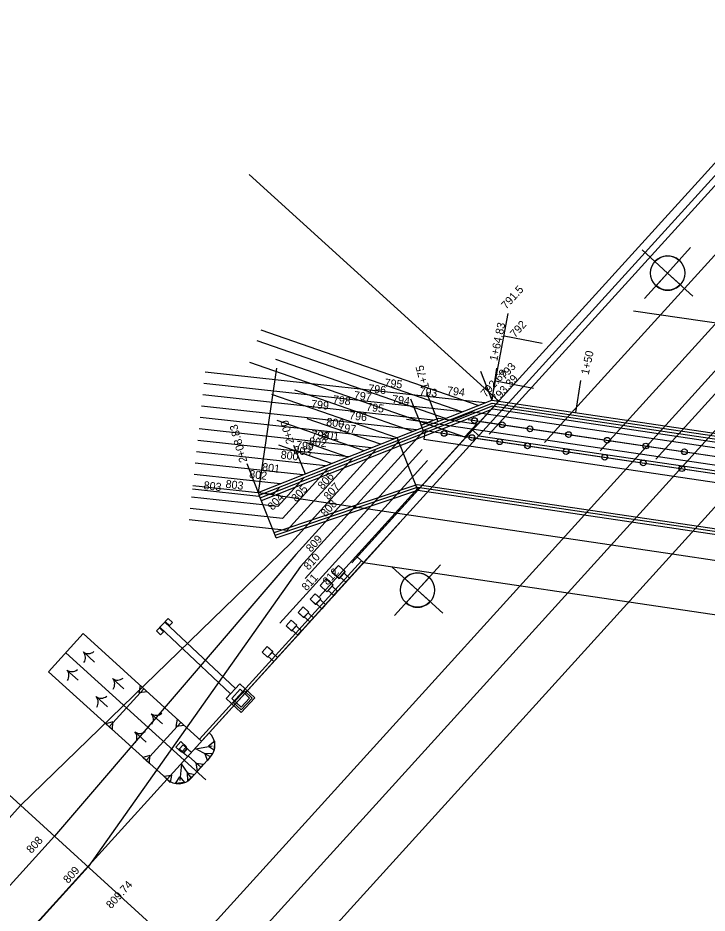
# Model space of a CAD drawing. Extents: x 1465887 to 1476191, y 569684 to 581027.
# Drawn here: x 1469715.4 to 1469836.1, y 573949.1 to 574105.8 of the extents above; entities that cross this region are included whole.
import ezdxf

# ---------------------------------------------------------------- set-up
doc = ezdxf.new("R2010")
doc.units = 0
for name, color, linetype in [('BR_P_Beam_Centerline', 7, 'Continuous'), ('BR_P_Brg_Centerline', 7, 'Continuous'), ('BR_P_Gen_Approach_Slab', 7, 'Continuous'), ('BR_P_Gen_Ground_Slope', 7, 'Continuous'), ('BR_P_Gen_Perforated_Pipe', 7, 'Continuous'), ('BR_P_Gen_Porous_Backfill', 7, 'Continuous'), ('BR_P_Gen_Profile_Grade', 7, 'Continuous'), ('BR_P_Gen_Slope_Protection', 7, 'Continuous'), ('BR_P_Rail_Object', 7, 'Continuous'), ('BR_P_Sub_Deep_Centerline', 7, 'Continuous'), ('BR_P_Sub_Deep_Hidden', 7, 'Continuous'), ('BR_P_Sub_Foot_Hidden', 7, 'Continuous'), ('BR_P_Sub_Hidden', 7, 'Continuous'), ('BR_P_Sub_Object', 7, 'Continuous'), ('BR_X_Sub_Hidden', 7, 'Continuous'), ('Default', 7, 'Continuous'), ('DR_P_Cells', 7, 'Continuous'), ('DR_P_Ditch', 7, 'Continuous'), ('DR_P_Erosion_Control', 7, 'Continuous'), ('DR_P_Headwall', 7, 'Continuous'), ('DR_P_Paved_Gutter', 7, 'Continuous'), ('DR_P_Storm_Sewer', 7, 'Continuous'), ('GK_Drainage_Nodes', 7, 'Continuous'), ('GT_Project_Soil_Boring', 7, 'Continuous'), ('RD_P_Anchor_Assembly', 7, 'Continuous'), ('SC_Scratch1', 7, 'Continuous'), ('SC_Scratch2', 7, 'Continuous')]:
    doc.layers.add(name, color=color, linetype=linetype)

msp = doc.modelspace()

# ---------------------------------------------------------------- linework, layer by layer
at = {"layer": 'BR_P_Beam_Centerline'}
for p, q in [((1469797.88, 574032.91), (1469908.95, 574155.21)), ((1469807.6, 574031.47), (1469918.67, 574153.77)), ((1469817.33, 574030.03), (1469928.4, 574152.33)), ((1469827.05, 574028.59), (1469938.12, 574150.89))]:
    msp.add_line(p, q, dxfattribs=at)
at = {"layer": 'BR_P_Brg_Centerline'}
msp.add_line((1469783.43, 574035.55), (1469948.19, 574011.16), dxfattribs=at)
at = {"layer": 'BR_P_Gen_Approach_Slab'}
for p, q in [((1469796.09, 574032.67), (1469935.4, 574012.04)), ((1469775.92, 574010.46), (1469915.23, 573989.83))]:
    msp.add_line(p, q, dxfattribs=at)
at = {"layer": 'BR_P_Gen_Ground_Slope'}
for p, q in [((1469798.37, 574038.9), (1469801.25, 574054.05)), ((1469795.95, 574037.94), (1469757.95, 574051.14)), ((1469800.5, 574050.12), (1469807.16, 574048.86)), ((1469793.1, 574036.82), (1469757.29, 574049.25)), ((1469793.98, 574032.28), (1469755.98, 574045.47)), ((1469790.25, 574035.69), (1469760.55, 574046)), ((1469797.14, 574038.41), (1469748.18, 574043.79)), ((1469793.15, 574036.84), (1469747.96, 574041.8)), ((1469799.01, 574042.26), (1469805.67, 574041)), ((1469784.55, 574033.43), (1469763.85, 574040.62)), ((1469788.11, 574035.38), (1469747.75, 574039.81)), ((1469781.7, 574032.31), (1469759.84, 574039.9)), ((1469785.19, 574033.69), (1469747.53, 574037.82)), ((1469781.21, 574032.11), (1469747.31, 574035.84)), ((1469778.85, 574031.18), (1469766, 574035.64)), ((1469776, 574030.05), (1469760.78, 574035.34)), ((1469777.23, 574030.54), (1469747.09, 574033.85)), ((1469786.61, 574033.71), (1469764.86, 574009.76)), ((1469773.25, 574028.96), (1469746.87, 574031.86)), ((1469770.3, 574027.8), (1469761.04, 574031.01)), ((1469782.39, 574032.04), (1469764.06, 574011.86)), ((1469773.15, 574028.93), (1469765.78, 574031.49)), ((1469769.26, 574027.39), (1469746.65, 574029.87)), ((1469778.17, 574030.38), (1469763.27, 574013.96)), ((1469786.16, 574030.24), (1469765.66, 574007.67)), ((1469765.28, 574025.81), (1469746.44, 574027.88)), ((1469787.11, 574028.32), (1469761.25, 573999.84)), ((1469773.96, 574028.71), (1469762.47, 574016.06)), ((1469769.74, 574027.04), (1469761.68, 574018.16)), ((1469761.3, 574024.24), (1469746.22, 574025.9)), ((1469765.53, 574025.37), (1469760.88, 574020.26)), ((1469757.58, 574022.04), (1469745.94, 574023.32)), ((1469760.09, 574022.36), (1469746, 574023.91)), ((1469761.31, 574023.71), (1469760.09, 574022.36)), ((1469785.46, 574023.53), (1469768.19, 574004.51)), ((1469760.88, 574020.26), (1469745.78, 574021.92)), ((1469761.68, 574018.16), (1469745.56, 574019.93)), ((1469762.47, 574016.06), (1469745.35, 574017.94)), ((1469763.27, 574013.96), (1469715.85, 573967.97)), ((1469764.06, 574011.86), (1469721.77, 573962.59)), ((1469764.86, 574009.76), (1469727.69, 573957.21)), ((1469715.85, 573967.97), (1469695.33, 573945.37)), ((1469721.77, 573962.59), (1469701.25, 573940)), ((1469727.69, 573957.21), (1469707.18, 573934.62))]:
    msp.add_line(p, q, dxfattribs=at)
at = {"layer": 'BR_P_Gen_Perforated_Pipe'}
for p, q in [((1469757.82, 574021.79), (1469798.49, 574037.87)), ((1469758.01, 574021.32), (1469798.55, 574037.36)), ((1469798.49, 574037.87), (1469942.86, 574016.5)), ((1469798.55, 574037.36), (1469942.47, 574016.05)), ((1469760.26, 574015.76), (1469785.31, 574024.15)), ((1469760.42, 574015.29), (1469785.35, 574023.64)), ((1469785.31, 574024.15), (1469929.51, 574002.81)), ((1469785.35, 574023.64), (1469929.29, 574002.33))]:
    msp.add_line(p, q, dxfattribs=at)
at = {"layer": 'BR_P_Gen_Porous_Backfill'}
for p, q in [((1469760.58, 574014.81), (1469785.4, 574023.13)), ((1469785.4, 574023.13), (1469929.06, 574001.86)), ((1469760.58, 574014.81), (1469757.64, 574022.25))]:
    msp.add_line(p, q, dxfattribs=at)
at = {"layer": 'BR_P_Gen_Profile_Grade'}
msp.add_line((1465892.5, 569689.56), (1476184.47, 581022.69), dxfattribs=at)
at = {"layer": 'BR_P_Gen_Slope_Protection'}
for p, q in [((1469757.45, 574022.72), (1469798.37, 574038.9)), ((1469798.37, 574038.9), (1469943.64, 574017.39)), ((1469757.64, 574022.25), (1469798.43, 574038.39)), ((1469798.43, 574038.39), (1469942.04, 574017.13)), ((1469757.45, 574022.72), (1469757.64, 574022.25))]:
    msp.add_line(p, q, dxfattribs=at)
at = {"layer": 'BR_P_Rail_Object'}
for p, q in [((1469774.81, 574011.47), (1469927.02, 574179.08)), ((1469775.92, 574010.46), (1469928.13, 574178.07)), ((1469796.09, 574032.67), (1469794.98, 574033.68)), ((1469775.92, 574010.46), (1469774.81, 574011.47))]:
    msp.add_line(p, q, dxfattribs=at)
at = {"layer": 'BR_P_Sub_Deep_Centerline'}
for p, q in [((1469794.19, 574035.48), (1469943.45, 574013.38)), ((1469789.4, 574033.15), (1469943.18, 574010.39))]:
    msp.add_line(p, q, dxfattribs=at)
at = {"layer": 'BR_P_Sub_Deep_Hidden'}
for centre in [(1469795.32, 574035.31), (1469800.18, 574034.59), (1469805.04, 574033.87), (1469790.01, 574033.06), (1469794.88, 574032.34), (1469811.8, 574032.87), (1469818.56, 574031.87), (1469799.74, 574031.62), (1469804.6, 574030.9), (1469825.32, 574030.87), (1469811.36, 574029.9), (1469818.12, 574028.9), (1469832.08, 574029.87), (1469824.88, 574027.9), (1469831.64, 574026.9)]:
    msp.add_circle(centre, 0.5, dxfattribs=at)
at = {"layer": 'BR_P_Sub_Foot_Hidden'}
for p, q in [((1469791.32, 574035.4), (1469795.04, 574036.87)), ((1469795.04, 574036.87), (1469943.7, 574014.86)), ((1469786.67, 574033.56), (1469786.45, 574032.07)), ((1469786.45, 574032.07), (1469944.6, 574008.66))]:
    msp.add_line(p, q, dxfattribs=at)
at = {"layer": 'BR_P_Sub_Hidden'}
for p, q in [((1469796.32, 574035.16), (1469939.21, 574014.01)), ((1469793.9, 574032.49), (1469936.78, 574011.33))]:
    msp.add_line(p, q, dxfattribs=at)
at = {"layer": 'BR_P_Sub_Object'}
for p, q in [((1469785.97, 574034.54), (1469789.01, 574035.74)), ((1469789.01, 574035.74), (1469795.92, 574034.71)), ((1469786.34, 574033.61), (1469785.97, 574034.54)), ((1469795.72, 574034.74), (1469793.7, 574032.52)), ((1469795.92, 574034.71), (1469793.9, 574032.49)), ((1469796.32, 574035.16), (1469795.92, 574034.71)), ((1469786.34, 574033.61), (1469793.9, 574032.49))]:
    msp.add_line(p, q, dxfattribs=at)
msp.add_lwpolyline([(1469793.7, 574032.52), (1469793.9, 574032.49), (1469795.92, 574034.71), (1469795.72, 574034.74)], close=True, dxfattribs=at)
at = {"layer": 'BR_X_Sub_Hidden'}
msp.add_line((1469968.46, 574033.03), (1469823.18, 574054.48), dxfattribs=at)
at = {"layer": 'Default'}
msp.add_line((1469756.32, 573988.88), (1469655.12, 573877.44), dxfattribs=at)
at = {"layer": 'DR_P_Cells'}
for points in [[(1469754.26, 573989.23), (1469751.86, 573986.68), (1469754.48, 573984.22), (1469756.87, 573986.78)], [(1469752.81, 573986.71), (1469754.29, 573988.29), (1469755.93, 573986.75), (1469754.45, 573985.17)], [(1469755.06, 573988.02), (1469753.12, 573985.95), (1469754.46, 573984.7), (1469756.4, 573986.76)]]:
    msp.add_lwpolyline(points, close=True, dxfattribs=at)
at = {"layer": 'DR_P_Ditch'}
msp.add_line((1469723.79, 573994.7), (1469748.27, 573972.47), dxfattribs=at)
at = {"layer": 'DR_P_Erosion_Control'}
for p, q in [((1469720.76, 573991.37), (1469726.81, 573998.03)), ((1469726.81, 573998.03), (1469747.54, 573979.21)), ((1469728.8, 573993.05), (1469726.84, 573994.83)), ((1469725.92, 573989.87), (1469723.96, 573991.66)), ((1469720.76, 573991.37), (1469741.49, 573972.55)), ((1469733.92, 573988.4), (1469731.96, 573990.18)), ((1469731.04, 573985.23), (1469729.08, 573987.01)), ((1469731.36, 573981.73), (1469737.42, 573988.39)), ((1469740.7, 573982.24), (1469738.74, 573984.02)), ((1469737.85, 573975.84), (1469743.9, 573982.5)), ((1469737.82, 573979.07), (1469735.86, 573980.85)), ((1469748.89, 573980.69), (1469747.54, 573979.21)), ((1469747.39, 573974.64), (1469745.24, 573976.6)), ((1469749.09, 573976.45), (1469745.73, 573972.75))]:
    msp.add_line(p, q, dxfattribs=at)
for points in [[(1469736.85, 573988.93), (1469737.99, 573987.86), (1469736.63, 573987.67)], [(1469736.85, 573988.93), (1469737.99, 573987.86), (1469736.63, 573987.67)], [(1469730.78, 573982.24), (1469731.95, 573981.21), (1469732.02, 573982.59)], [(1469743.34, 573983.04), (1469744.48, 573981.97), (1469743.11, 573981.78)], [(1469743.34, 573983.04), (1469744.48, 573981.97), (1469743.11, 573981.78)], [(1469749.82, 573977.64), (1469749.86, 573979.2), (1469748.76, 573978.37)], [(1469737.26, 573976.35), (1469738.44, 573975.32), (1469738.5, 573976.7)], [(1469748.57, 573975.8), (1469749.52, 573977.04), (1469748.13, 573977.01)], [(1469747.86, 573975.2), (1469746.83, 573974.03), (1469746.59, 573975.39)], [(1469742.06, 573972.01), (1469740.92, 573973.08), (1469742.29, 573973.28)], [(1469744.56, 573971.97), (1469743, 573971.81), (1469743.76, 573972.97)], [(1469746.31, 573973.36), (1469745.13, 573972.32), (1469745.07, 573973.7)]]:
    msp.add_lwpolyline(points, close=True, dxfattribs=at)
for points in [[(1469749.09, 573976.45), (1469746.52, 573977.9), (1469749.41, 573978.41)], [(1469745.7, 573972.79), (1469744.05, 573975.24), (1469743.76, 573972.32)]]:
    msp.add_lwpolyline(points, dxfattribs=at)
for centre, radius, start, end in [((1469727.71, 573996.06), 1.51, 234.7784, 310.04), ((1469725.7, 573993.85), 1.51, 325.4729, 40.7345), ((1469724.83, 573992.89), 1.51, 234.7784, 310.04), ((1469722.81, 573990.67), 1.51, 325.4729, 40.7345), ((1469732.83, 573991.41), 1.51, 234.7784, 310.04), ((1469730.82, 573989.2), 1.51, 325.4729, 40.7345), ((1469729.95, 573988.24), 1.51, 234.7784, 310.04), ((1469727.93, 573986.02), 1.51, 325.4729, 40.7345), ((1469739.61, 573985.25), 1.51, 234.7784, 310.04), ((1469737.6, 573983.04), 1.51, 325.4729, 40.7345), ((1469736.73, 573982.08), 1.51, 234.7784, 310.04), ((1469734.72, 573979.86), 1.51, 325.4729, 40.7345), ((1469746.87, 573978.47), 3, 317.7564, 47.7564), ((1469743.51, 573974.77), 3, 227.7564, 317.7564)]:
    msp.add_arc(centre, radius, start, end, dxfattribs=at)
at = {"layer": 'DR_P_Headwall'}
msp.add_lwpolyline([(1469740.16, 573999.04), (1469740.88, 573998.36), (1469740.37, 573997.81), (1469739.64, 573998.5), (1469741.7, 574000.68), (1469742.42, 574000), (1469741.91, 573999.45), (1469741.18, 574000.14)], dxfattribs=at)
at = {"layer": 'DR_P_Paved_Gutter'}
for p, q in [((1469775.55, 574010.8), (1469747.17, 573979.55)), ((1469775.92, 574010.46), (1469748.89, 573980.69)), ((1469747.54, 573979.21), (1469747.17, 573979.55))]:
    msp.add_line(p, q, dxfattribs=at)
at = {"layer": 'DR_P_Storm_Sewer'}
for p, q in [((1469753.49, 573988.41), (1469741.1, 574000.05)), ((1469752.63, 573987.5), (1469740.24, 573999.14))]:
    msp.add_line(p, q, dxfattribs=at)
at = {"layer": 'GK_Drainage_Nodes'}
for p, q in [((1469740.67, 573999.59), (1469740.67, 573999.59)), ((1469740.67, 573999.59), (1469740.67, 573999.59)), ((1469740.67, 573999.59), (1469740.67, 573999.59)), ((1469740.67, 573999.59), (1469740.67, 573999.59)), ((1469740.67, 573999.59), (1469740.67, 573999.59)), ((1469741.4, 573998.91), (1469741.4, 573998.91)), ((1469753.06, 573987.95), (1469753.06, 573987.95)), ((1469753.55, 573987.5), (1469753.55, 573987.5)), ((1469754.09, 573986.98), (1469754.09, 573986.98)), ((1469754.09, 573986.98), (1469754.09, 573986.98)), ((1469755.11, 573987.52), (1469755.11, 573987.52)), ((1469753.63, 573985.94), (1469753.63, 573985.94)), ((1469754.37, 573986.73), (1469754.37, 573986.73)), ((1469754.37, 573986.73), (1469754.37, 573986.73)), ((1469754.37, 573986.73), (1469754.37, 573986.73)), ((1469755.19, 573985.96), (1469755.19, 573985.96)), ((1469755.67, 573985.5), (1469755.67, 573985.5))]:
    msp.add_line(p, q, dxfattribs=at)
at = {"layer": 'GT_Project_Soil_Boring'}
for p, q in [((1469829.14, 574061.13), (1469833.17, 574065.58)), ((1469829.14, 574061.13), (1469824.69, 574065.17)), ((1469829.14, 574061.13), (1469826.92, 574063.15)), ((1469831.15, 574063.36), (1469829.14, 574061.13)), ((1469829.14, 574061.13), (1469825.1, 574056.69)), ((1469827.12, 574058.91), (1469829.14, 574061.13)), ((1469829.14, 574061.13), (1469833.58, 574057.1)), ((1469829.14, 574061.13), (1469831.36, 574059.12)), ((1469785.35, 574005.65), (1469780.91, 574009.68)), ((1469785.35, 574005.65), (1469789.39, 574010.09)), ((1469785.35, 574005.65), (1469783.13, 574007.66)), ((1469787.37, 574007.87), (1469785.35, 574005.65)), ((1469785.35, 574005.65), (1469781.32, 574001.2)), ((1469783.34, 574003.43), (1469785.35, 574005.65)), ((1469785.35, 574005.65), (1469789.8, 574001.61)), ((1469785.35, 574005.65), (1469787.57, 574003.63))]:
    msp.add_line(p, q, dxfattribs=at)
for centre in [(1469829.14, 574061.13), (1469785.35, 574005.65)]:
    msp.add_circle(centre, 3, dxfattribs=at)
for centre, start, end in [((1469829.14, 574061.13), 47.7565, 137.7565), ((1469829.14, 574061.13), 227.7565, 317.7565), ((1469785.35, 574005.65), 47.7565, 137.7565), ((1469785.35, 574005.65), 227.7565, 317.7565)]:
    msp.add_arc(centre, 3, start, end, dxfattribs=at)
at = {"layer": 'RD_P_Anchor_Assembly'}
for q in [(1469782.44, 574017.64), (1469756.33, 573988.88)]:
    msp.add_line((1469777.33, 574012.02), q, dxfattribs=at)
for points in [[(1469772.71, 574008.88), (1469771.61, 574007.66), (1469770.39, 574008.76), (1469771.49, 574009.98)], [(1469771.49, 574009.98), (1469770.39, 574008.76), (1469771.61, 574007.66), (1469772.71, 574008.88)], [(1469772.71, 574008.88), (1469771.61, 574007.67), (1469770.4, 574008.77), (1469771.5, 574009.98)], [(1469771.5, 574009.98), (1469770.4, 574008.77), (1469771.61, 574007.67), (1469772.71, 574008.88)], [(1469770.6, 574006.56), (1469769.5, 574005.34), (1469768.28, 574006.44), (1469769.39, 574007.66)], [(1469768.28, 574006.44), (1469769.39, 574007.66), (1469770.6, 574006.56), (1469769.5, 574005.34)], [(1469770.6, 574006.55), (1469769.5, 574005.34), (1469768.28, 574006.44), (1469769.38, 574007.65)], [(1469768.28, 574006.44), (1469769.38, 574007.65), (1469770.6, 574006.55), (1469769.5, 574005.34)], [(1469773.46, 574007.75), (1469772.8, 574007.03), (1469771.83, 574007.91), (1469772.49, 574008.64)], [(1469771.83, 574007.91), (1469772.49, 574008.64), (1469773.46, 574007.75), (1469772.8, 574007.03)], [(1469773.46, 574007.75), (1469772.8, 574007.02), (1469771.83, 574007.9), (1469772.49, 574008.63)], [(1469771.83, 574007.9), (1469772.49, 574008.63), (1469773.46, 574007.75), (1469772.8, 574007.02)], [(1469771.36, 574005.44), (1469770.7, 574004.71), (1469769.73, 574005.6), (1469770.39, 574006.32)], [(1469770.39, 574006.32), (1469769.73, 574005.6), (1469770.7, 574004.71), (1469771.36, 574005.44)], [(1469771.36, 574005.44), (1469770.7, 574004.71), (1469769.73, 574005.59), (1469770.39, 574006.32)], [(1469770.39, 574006.32), (1469769.73, 574005.59), (1469770.7, 574004.71), (1469771.36, 574005.44)], [(1469768.4, 574004.13), (1469767.51, 574003.16), (1469766.54, 574004.04), (1469767.42, 574005.01)], [(1469767.42, 574005.01), (1469766.54, 574004.04), (1469767.51, 574003.16), (1469768.4, 574004.13)], [(1469768.4, 574004.13), (1469767.52, 574003.16), (1469766.55, 574004.04), (1469767.43, 574005.01)], [(1469767.43, 574005.01), (1469766.55, 574004.04), (1469767.52, 574003.16), (1469768.4, 574004.13)], [(1469766.3, 574001.81), (1469765.41, 574000.84), (1469764.44, 574001.72), (1469765.32, 574002.7)], [(1469765.32, 574002.7), (1469764.44, 574001.72), (1469765.41, 574000.84), (1469766.3, 574001.81)], [(1469766.3, 574001.82), (1469765.42, 574000.85), (1469764.45, 574001.73), (1469765.33, 574002.7)], [(1469765.33, 574002.7), (1469764.45, 574001.73), (1469765.42, 574000.85), (1469766.3, 574001.82)], [(1469769.26, 574003.12), (1469768.6, 574002.4), (1469767.62, 574003.28), (1469768.29, 574004.01)], [(1469769.26, 574003.12), (1469768.6, 574002.4), (1469767.62, 574003.28), (1469768.29, 574004.01)], [(1469769.26, 574003.13), (1469768.6, 574002.4), (1469767.63, 574003.28), (1469768.29, 574004.01)], [(1469769.26, 574003.13), (1469768.6, 574002.4), (1469767.63, 574003.28), (1469768.29, 574004.01)], [(1469767.16, 574000.81), (1469766.5, 574000.08), (1469765.52, 574000.96), (1469766.19, 574001.69)], [(1469765.52, 574000.96), (1469766.19, 574001.69), (1469767.16, 574000.81), (1469766.5, 574000.08)], [(1469767.16, 574000.81), (1469766.5, 574000.09), (1469765.53, 574000.97), (1469766.19, 574001.7)], [(1469765.53, 574000.97), (1469766.19, 574001.7), (1469767.16, 574000.81), (1469766.5, 574000.09)], [(1469764.2, 573999.5), (1469763.32, 573998.53), (1469762.34, 573999.42), (1469763.23, 574000.39)], [(1469764.2, 573999.5), (1469763.32, 573998.53), (1469762.34, 573999.42), (1469763.23, 574000.39)], [(1469764.19, 573999.5), (1469763.31, 573998.53), (1469762.34, 573999.41), (1469763.22, 574000.38)], [(1469764.19, 573999.5), (1469763.31, 573998.53), (1469762.34, 573999.41), (1469763.22, 574000.38)], [(1469765.06, 573998.5), (1469764.39, 573997.77), (1469763.42, 573998.65), (1469764.08, 573999.38)], [(1469764.08, 573999.38), (1469763.42, 573998.65), (1469764.39, 573997.77), (1469765.06, 573998.5)], [(1469765.06, 573998.5), (1469764.4, 573997.77), (1469763.43, 573998.65), (1469764.09, 573999.38)], [(1469764.09, 573999.38), (1469763.43, 573998.65), (1469764.4, 573997.77), (1469765.06, 573998.5)], [(1469760, 573994.88), (1469759.11, 573993.91), (1469758.14, 573994.79), (1469759.03, 573995.76)], [(1469759.03, 573995.76), (1469758.14, 573994.79), (1469759.11, 573993.91), (1469760, 573994.88)], [(1469759.99, 573994.87), (1469759.11, 573993.9), (1469758.14, 573994.78), (1469759.02, 573995.76)], [(1469759.02, 573995.76), (1469758.14, 573994.78), (1469759.11, 573993.9), (1469759.99, 573994.87)], [(1469760.86, 573993.87), (1469760.2, 573993.15), (1469759.22, 573994.03), (1469759.89, 573994.76)], [(1469759.89, 573994.76), (1469759.22, 573994.03), (1469760.2, 573993.15), (1469760.86, 573993.87)], [(1469760.85, 573993.87), (1469760.19, 573993.14), (1469759.22, 573994.02), (1469759.88, 573994.75)], [(1469759.88, 573994.75), (1469759.22, 573994.02), (1469760.19, 573993.14), (1469760.85, 573993.87)], [(1469744.9, 573978.25), (1469744.01, 573977.28), (1469743.04, 573978.16), (1469743.92, 573979.13)], [(1469743.92, 573979.13), (1469743.04, 573978.16), (1469744.01, 573977.28), (1469744.9, 573978.25)], [(1469744.89, 573978.25), (1469744.01, 573977.27), (1469743.04, 573978.16), (1469743.92, 573979.13)], [(1469743.92, 573979.13), (1469743.04, 573978.16), (1469744.01, 573977.27), (1469744.89, 573978.25)], [(1469745.03, 573977.91), (1469744.37, 573977.18), (1469743.64, 573977.84), (1469744.3, 573978.57)], [(1469744.3, 573978.57), (1469743.64, 573977.84), (1469744.37, 573977.18), (1469745.03, 573977.91)], [(1469745.76, 573977.25), (1469745.1, 573976.52), (1469744.12, 573977.4), (1469744.79, 573978.13)], [(1469744.79, 573978.13), (1469744.12, 573977.4), (1469745.1, 573976.52), (1469745.76, 573977.25)], [(1469745.75, 573977.24), (1469745.09, 573976.51), (1469744.12, 573977.4), (1469744.78, 573978.12)], [(1469744.78, 573978.12), (1469744.12, 573977.4), (1469745.09, 573976.51), (1469745.75, 573977.24)], [(1469745.76, 573977.25), (1469745.1, 573976.52), (1469744.37, 573977.18), (1469745.03, 573977.91)], [(1469745.03, 573977.91), (1469744.37, 573977.18), (1469745.1, 573976.52), (1469745.76, 573977.25)]]:
    msp.add_lwpolyline(points, close=True, dxfattribs=at)
at = {"layer": 'SC_Scratch1'}
for p, q in [((1465887.32, 569694.27), (1476179.29, 581027.4)), ((1465899.17, 569683.51), (1476191.13, 581016.64)), ((1469760.68, 574044.48), (1469757.45, 574022.72)), ((1469796.36, 574043.97), (1469798.37, 574038.9)), ((1469799.2, 574044.5), (1469798.37, 574038.9)), ((1469813.87, 574042.33), (1469813.04, 574036.73)), ((1469786.91, 574040.23), (1469788.91, 574035.16)), ((1469799.56, 574038.72), (1469773.84, 574010.4)), ((1469784.15, 574039.14), (1469786.16, 574034.07)), ((1469763.66, 574031.04), (1469765.67, 574025.97)), ((1469785.4, 574023.13), (1469781.76, 574032.33)), ((1469755.45, 574027.79), (1469757.45, 574022.72)), ((1469757.45, 574022.72), (1469828.79, 574012.16)), ((1469828.79, 574012.16), (1469875.83, 574005.19)), ((1469682.83, 573997.95), (1469788.76, 573901.75))]:
    msp.add_line(p, q, dxfattribs=at)
at = {"layer": 'SC_Scratch2'}
msp.add_line((1469799.56, 574038.72), (1469755.88, 574078.39), dxfattribs=at)

# ---------------------------------------------------------------- texts
at = {"layer": 'BR_P_Gen_Ground_Slope'}
for s, rotation, p in [('791.5', 47.7564, (1469800.88, 574054.7)), ('792', 47.7564, (1469802.43, 574049.73)), ('793', 47.7564, (1469800.57, 574042.39)), ('792.69', 47.7564, (1469797.29, 574039.3)), ('795', 353.2119, (1469779.51, 574041.29)), ('793.39', 47.7564, (1469799.2, 574038.34)), ('797', 353.2119, (1469774.13, 574039.1)), ('796', 353.2119, (1469776.66, 574040.29)), ('793', 353.2119, (1469785.63, 574039.79)), ('794', 353.2119, (1469790.46, 574039.92)), ('799', 353.2119, (1469766.64, 574037.57)), ('798', 353.2119, (1469770.46, 574038.36)), ('794', 353.2119, (1469780.83, 574038.4)), ('795', 353.2119, (1469776.3, 574037.06)), ('800', 353.2119, (1469769.32, 574034.43)), ('796', 353.2119, (1469773.32, 574035.56)), ('797', 353.2119, (1469771.42, 574033.46)), ('802', 353.2119, (1469766.28, 574031.01)), ('798', 353.2119, (1469766.69, 574032.23)), ('801', 353.2119, (1469768.44, 574032.22)), ('803', 353.2119, (1469763.57, 574029.5)), ('799', 353.2119, (1469763.99, 574030.4)), ('800', 353.2119, (1469761.33, 574028.69)), ('801', 353.2119, (1469758.08, 574026.53)), ('802', 353.2119, (1469755.82, 574025.3)), ('806', 47.7564, (1469768.73, 574023.16)), ('803', 353.2119, (1469747.83, 574023.34)), ('803', 353.2119, (1469751.68, 574023.57)), ('805', 47.7564, (1469764.13, 574020.97)), ('807', 47.7564, (1469769.78, 574021.33)), ('804', 47.7564, (1469759.99, 574019.51)), ('808', 47.7564, (1469769.27, 574018.36)), ('809', 47.7564, (1469766.69, 574012.18)), ('810', 47.7564, (1469766.28, 574009.04)), ('812', 47.7564, (1469769.6, 574006.41)), ('811', 47.7564, (1469765.94, 574005.43)), ('808', 47.7564, (1469717.75, 573959.47)), ('809', 47.7564, (1469724.18, 573954.22)), ('809.74', 47.7564, (1469731.7, 573949.79))]:
    msp.add_text(s, height=1.4, rotation=rotation, dxfattribs=at).set_placement(p)
at = {"layer": 'SC_Scratch1'}
for s, rotation, p in [('1+64.83', 77.7564, (1469799.3, 574045.65)), ('1+50', 77.7564, (1469815.31, 574043.25)), ('1+75', 105.2907, (1469787.44, 574041.05)), ('2+08.83', 105.2907, (1469755.56, 574028.18)), ('2+00', 105.2907, (1469763.77, 574031.43))]:
    msp.add_text(s, height=1.4, rotation=rotation, dxfattribs=at).set_placement(p)

doc.saveas('drawing.dxf')
